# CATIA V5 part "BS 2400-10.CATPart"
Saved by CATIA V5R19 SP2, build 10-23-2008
Part number: BS 2400-10
Bounding box of the stored display mesh (mm): x -37.351 to 37.351, y -37.351 to 37.351, z 0 to 65
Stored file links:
  C:\Users\Bora\Desktop\3D Katı model\BS serisi\BS 2400\BS 2400-10.CATPart
  C:\Program Files\Dassault Systemes\B19\intel_a\reffiles\standard\MetricThickPitch.txt
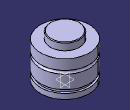
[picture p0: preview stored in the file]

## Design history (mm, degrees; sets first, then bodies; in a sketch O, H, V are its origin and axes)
Body1 (main body)
  Sketch1 on yz-plane, origin (0, 0, 0), H (0, 1, 0), V (0, 0, 1)
    point P1 (22.5, 64)
    point P3 (22.5, 64)
    point P7 (37.5, 38.5)
    point P9 (37.5, 38.5)
    point P10 (37.5, 33.5)
    point P14 (37.5, 33.5)
    line L1 (22.5, 64) -> (22.5, 54)
    arc A1 centre (21.5, 64) radius 1 from (22.5, 64) to (21.5, 65) ccw
    line L2 (37.5, 0) -> (37.5, 8)
    line L3 (37.5, 38.5) -> (37.5, 54)
    arc A2 centre (37.5, 36) radius 2.5 from (37.5, 38.5) to (37.5, 33.5) ccw
    line L4 (34.5, 13) -> (34.5, 8)
    line L5 (37.5, 13) -> (37.5, 33.5)
    line L6 (21.5, 65) -> (0, 65)
    point P15 (0, 65)
    line L7 (22.5, 54) -> (37.5, 54)
    line L8 (0, 0) -> (37.5, 0)
    line L9 (34.5, 13) -> (37.5, 13)
    line L10 (34.5, 8) -> (37.5, 8)
    coincidence: P15 V, P1 P3, P7 P9, P10 P14
    tangency: L6 A1
    horizontal: L7 H, L8 H, L9 H, L10 H
  Shaft1: profile Sketch1, axis Sketch1.V, angle 360
  Sketch2 on face of Shaft1 from Sketch1.L8, origin (0, 0, 0), H (1, 0, 0), V (0, -1, 0)
    point P1 (20, 0)
    distance P1 V = 20
  Hole1: placed by Sketch2, at (20, 0, 0) direction (0, 0, 1), diameter 6.647, depth 5, threaded "M8", thread diameter 8, thread depth 5, pitch 1.25
  CircPattern1: of Hole1, instances 4, angular step 90, axis from xy-plane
